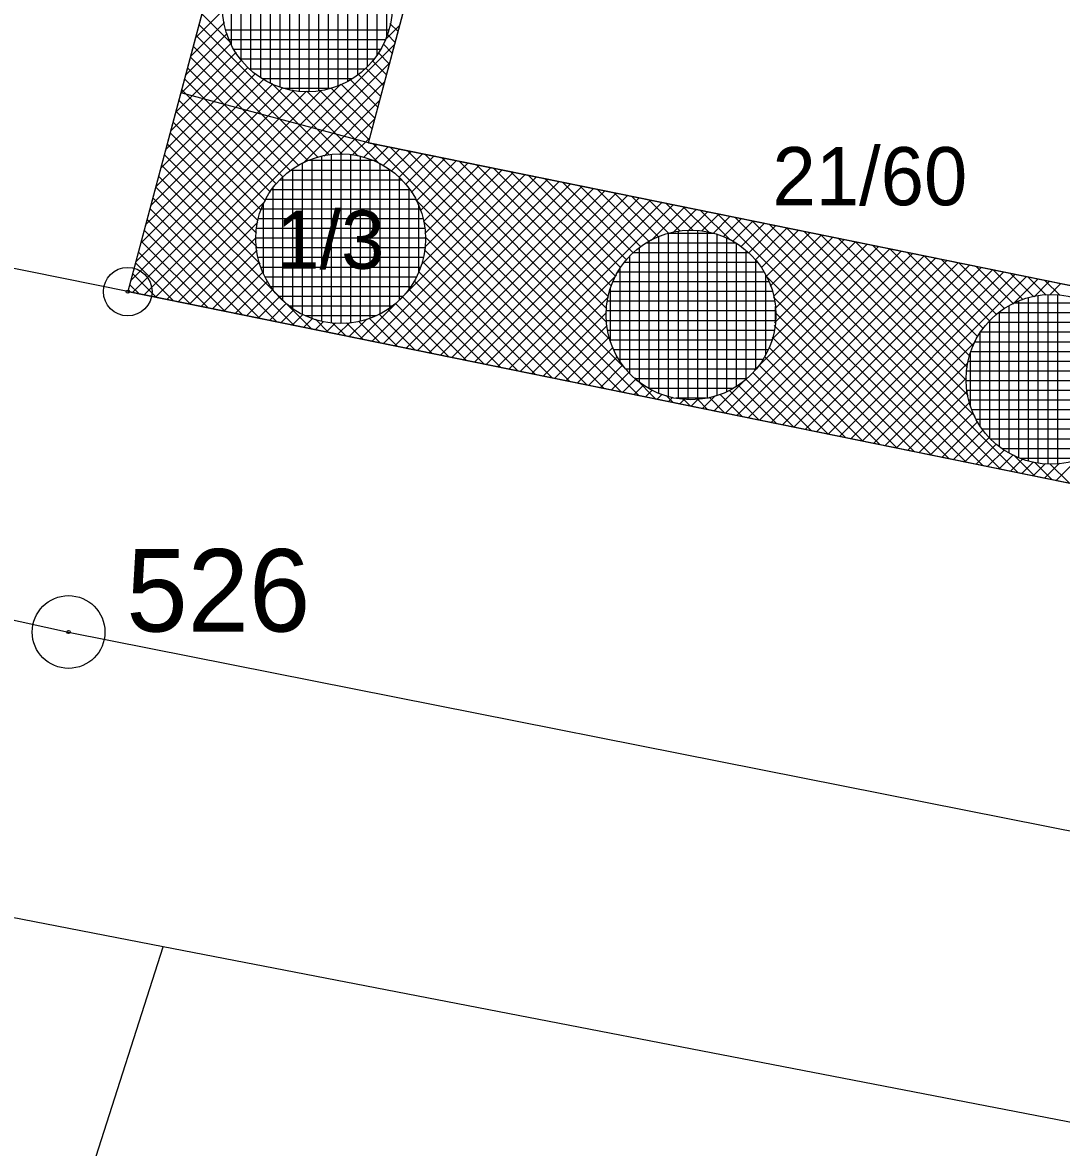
# Model space of a CAD drawing. Extents: x -566461 to -565198, y -1096301 to -1095707.
# Drawn here: x -565856.17 to -565834.75, y -1096125.98 to -1096102.78 of the extents above; entities that cross this region are included whole.
import ezdxf

# ---------------------------------------------------------------- set-up
doc = ezdxf.new("R2010")
doc.units = 0
for name, color, linetype in [('Vrstva 1', 7, 'Continuous'), ('Vrstva 17', 7, 'Continuous'), ('Vrstva 24', 7, 'Continuous'), ('Vrstva 40', 7, 'Continuous'), ('Vrstva 41', 7, 'Continuous'), ('Vrstva 42', 7, 'Continuous'), ('Vrstva 44', 7, 'Continuous')]:
    doc.layers.add(name, color=color, linetype=linetype)

msp = doc.modelspace()

# ---------------------------------------------------------------- linework, layer by layer
at = {"layer": 'Vrstva 1'}
for p, q in [((-565832.07, -1096026.09), (-565854, -1096108.33)), ((-565849.04, -1096105.26), (-565838.03, -1096063.98)), ((-565922.65, -1096100.77), (-565855.22, -1096115.35)), ((-565849.04, -1096105.26), (-565748.22, -1096125.78)), ((-565854, -1096108.33), (-565860.88, -1096106.94)), ((-565697.28, -1096140.23), (-565854, -1096108.33)), ((-565855.22, -1096115.35), (-565699.29, -1096146.31)), ((-565853.27, -1096121.84), (-565856.42, -1096121.23)), ((-565894.7, -1096251.46), (-565853.27, -1096121.84)), ((-565830.85, -1096126.18), (-565853.27, -1096121.84))]:
    msp.add_line(p, q, dxfattribs=at)
at = {"layer": 'Vrstva 24'}
for centre, radius in [((-565854, -1096108.33), 0.5), ((-565854, -1096108.33), 0.0327), ((-565855.22, -1096115.35), 0.75), ((-565855.22, -1096115.35), 0.0327)]:
    msp.add_circle(centre, radius, dxfattribs=at)
at = {"layer": 'Vrstva 41'}
for p, q in [((-565852.604, -1096103.094), (-565852.036, -1096102.526)), ((-565852.472, -1096102.6), (-565851.875, -1096103.197)), ((-565852.707, -1096103.479), (-565852.008, -1096102.781)), ((-565852.532, -1096102.823), (-565849.839, -1096105.516)), ((-565848.705, -1096103.155), (-565848.396, -1096102.846)), ((-565848.596, -1096102.799), (-565848.428, -1096102.967)), ((-565852.809, -1096103.865), (-565851.951, -1096103.007)), ((-565852.591, -1096103.047), (-565850.074, -1096105.564)), ((-565848.655, -1096103.023), (-565848.488, -1096103.19)), ((-565853.665, -1096108.398), (-565848.499, -1096103.232)), ((-565852.912, -1096104.251), (-565851.869, -1096103.208)), ((-565852.651, -1096103.27), (-565850.284, -1096105.636)), ((-565848.738, -1096103.223), (-565848.547, -1096103.413)), ((-565853.118, -1096105.022), (-565851.65, -1096103.554)), ((-565853.015, -1096104.636), (-565851.768, -1096103.39)), ((-565852.71, -1096103.493), (-565850.475, -1096105.729)), ((-565848.84, -1096103.403), (-565848.607, -1096103.637)), ((-565853.43, -1096108.446), (-565848.602, -1096103.617)), ((-565853.221, -1096105.408), (-565851.515, -1096103.702)), ((-565852.77, -1096103.716), (-565850.645, -1096105.841)), ((-565849.096, -1096103.713), (-565848.726, -1096104.083)), ((-565848.96, -1096103.566), (-565848.667, -1096103.86)), ((-565853.426, -1096106.179), (-565851.197, -1096103.95)), ((-565853.324, -1096105.794), (-565851.364, -1096103.834)), ((-565852.829, -1096103.94), (-565850.799, -1096105.97)), ((-565850.385, -1096105.683), (-565848.705, -1096104.003)), ((-565849.417, -1096103.958), (-565848.845, -1096104.53)), ((-565849.248, -1096103.844), (-565848.786, -1096104.306)), ((-565853.941, -1096108.108), (-565850.006, -1096104.173)), ((-565853.9, -1096108.35), (-565849.605, -1096104.055)), ((-565853.838, -1096107.722), (-565850.315, -1096104.199)), ((-565853.735, -1096107.336), (-565850.574, -1096104.176)), ((-565853.632, -1096106.951), (-565850.805, -1096104.124)), ((-565853.529, -1096106.565), (-565851.012, -1096104.048)), ((-565852.889, -1096104.163), (-565850.937, -1096106.115)), ((-565851.037, -1096104.035), (-565849.571, -1096105.501)), ((-565850.621, -1096104.168), (-565849.253, -1096105.536)), ((-565850.307, -1096104.2), (-565848.811, -1096105.695)), ((-565850.045, -1096104.179), (-565849.024, -1096105.2)), ((-565849.812, -1096104.128), (-565848.964, -1096104.976)), ((-565849.603, -1096104.054), (-565848.905, -1096104.753)), ((-565852.948, -1096104.386), (-565851.058, -1096106.277)), ((-565849.953, -1096105.534), (-565848.808, -1096104.389)), ((-565853.008, -1096104.61), (-565851.162, -1096106.456)), ((-565853.067, -1096104.833), (-565851.247, -1096106.653)), ((-565849.636, -1096105.5), (-565848.911, -1096104.775)), ((-565853.127, -1096105.056), (-565851.311, -1096106.872)), ((-565849.371, -1096105.518), (-565849.013, -1096105.16)), ((-565853.187, -1096105.28), (-565851.344, -1096107.122)), ((-565849.137, -1096105.567), (-565848.866, -1096105.295)), ((-565848.944, -1096105.28), (-565843.822, -1096110.402)), ((-565848.927, -1096105.639), (-565848.631, -1096105.343)), ((-565848.738, -1096105.733), (-565848.396, -1096105.391)), ((-565848.589, -1096105.352), (-565843.467, -1096110.474)), ((-565853.246, -1096105.503), (-565851.342, -1096107.407)), ((-565848.568, -1096105.846), (-565848.161, -1096105.439)), ((-565848.415, -1096105.976), (-565847.926, -1096105.487)), ((-565848.278, -1096106.122), (-565847.691, -1096105.535)), ((-565848.234, -1096105.424), (-565843.689, -1096109.969)), ((-565848.157, -1096106.284), (-565847.456, -1096105.582)), ((-565848.054, -1096106.463), (-565847.221, -1096105.63)), ((-565847.879, -1096105.496), (-565844.053, -1096109.322)), ((-565847.523, -1096105.569), (-565844.122, -1096108.97)), ((-565847.168, -1096105.641), (-565844.124, -1096108.685)), ((-565853.306, -1096105.726), (-565851.27, -1096107.761)), ((-565847.969, -1096106.662), (-565846.986, -1096105.678)), ((-565847.954, -1096107.778), (-565846.046, -1096105.869)), ((-565847.906, -1096106.882), (-565846.751, -1096105.726)), ((-565847.889, -1096107.43), (-565846.281, -1096105.822)), ((-565847.875, -1096107.133), (-565846.516, -1096105.774)), ((-565846.813, -1096105.713), (-565844.09, -1096108.437)), ((-565846.458, -1096105.786), (-565844.025, -1096108.218)), ((-565846.103, -1096105.858), (-565843.94, -1096108.021)), ((-565853.365, -1096105.949), (-565850.214, -1096109.101)), ((-565849.2, -1096109.307), (-565845.811, -1096105.917)), ((-565848.965, -1096109.355), (-565845.576, -1096105.965)), ((-565848.73, -1096109.403), (-565845.341, -1096106.013)), ((-565848.495, -1096109.45), (-565845.106, -1096106.061)), ((-565845.748, -1096105.93), (-565843.835, -1096107.843)), ((-565845.393, -1096106.002), (-565843.714, -1096107.682)), ((-565845.038, -1096106.075), (-565843.576, -1096107.537)), ((-565853.425, -1096106.173), (-565850.569, -1096109.028)), ((-565848.26, -1096109.498), (-565844.871, -1096106.109)), ((-565848.025, -1096109.546), (-565844.636, -1096106.156)), ((-565847.79, -1096109.594), (-565844.401, -1096106.204)), ((-565847.555, -1096109.642), (-565844.166, -1096106.252)), ((-565847.32, -1096109.69), (-565843.931, -1096106.3)), ((-565844.682, -1096106.147), (-565843.422, -1096107.408)), ((-565844.327, -1096106.219), (-565843.25, -1096107.296)), ((-565843.972, -1096106.292), (-565843.059, -1096107.204)), ((-565853.484, -1096106.396), (-565850.924, -1096108.956)), ((-565853.195, -1096108.494), (-565851.167, -1096106.465)), ((-565848.065, -1096106.441), (-565844.177, -1096110.329)), ((-565847.085, -1096109.737), (-565843.696, -1096106.348)), ((-565846.85, -1096109.785), (-565843.461, -1096106.396)), ((-565846.615, -1096109.833), (-565843.226, -1096106.443)), ((-565846.38, -1096109.881), (-565842.991, -1096106.491)), ((-565846.145, -1096109.929), (-565842.756, -1096106.539)), ((-565843.617, -1096106.364), (-565842.848, -1096107.133)), ((-565843.262, -1096106.436), (-565842.613, -1096107.085)), ((-565842.907, -1096106.508), (-565842.344, -1096107.072)), ((-565853.544, -1096106.619), (-565851.279, -1096108.884)), ((-565843.209, -1096107.276), (-565842.521, -1096106.587)), ((-565842.76, -1096107.109), (-565842.286, -1096106.635)), ((-565842.552, -1096106.581), (-565842.024, -1096107.108)), ((-565842.44, -1096107.072), (-565842.051, -1096106.683)), ((-565842.197, -1096106.653), (-565841.577, -1096107.272)), ((-565842.17, -1096107.085), (-565841.816, -1096106.73)), ((-565841.934, -1096107.132), (-565841.581, -1096106.778)), ((-565841.841, -1096106.725), (-565836.719, -1096111.847)), ((-565841.486, -1096106.797), (-565836.364, -1096111.92)), ((-565853.603, -1096106.843), (-565851.635, -1096108.811)), ((-565852.96, -1096108.542), (-565851.316, -1096106.897)), ((-565847.906, -1096106.883), (-565844.532, -1096110.257)), ((-565841.723, -1096107.203), (-565841.345, -1096106.826)), ((-565841.532, -1096107.295), (-565841.11, -1096106.874)), ((-565841.36, -1096107.407), (-565840.875, -1096106.922)), ((-565841.206, -1096107.535), (-565840.64, -1096106.97)), ((-565841.131, -1096106.87), (-565836.009, -1096111.992)), ((-565841.068, -1096107.68), (-565840.405, -1096107.017)), ((-565840.776, -1096106.942), (-565835.654, -1096112.064)), ((-565840.421, -1096107.014), (-565836.531, -1096110.904)), ((-565853.663, -1096107.066), (-565851.99, -1096108.739)), ((-565852.725, -1096108.589), (-565851.35, -1096107.214)), ((-565847.871, -1096107.201), (-565844.887, -1096110.185)), ((-565840.946, -1096107.841), (-565840.17, -1096107.065)), ((-565840.841, -1096108.019), (-565839.935, -1096107.113)), ((-565840.755, -1096108.216), (-565839.7, -1096107.161)), ((-565840.691, -1096108.434), (-565839.465, -1096107.209)), ((-565840.656, -1096108.682), (-565839.23, -1096107.257)), ((-565840.066, -1096107.087), (-565836.676, -1096110.476)), ((-565839.711, -1096107.159), (-565836.709, -1096110.161)), ((-565839.356, -1096107.231), (-565836.69, -1096109.896)), ((-565853.722, -1096107.289), (-565852.345, -1096108.667)), ((-565852.49, -1096108.637), (-565851.332, -1096107.479)), ((-565847.892, -1096107.463), (-565845.242, -1096110.113)), ((-565841.68, -1096110.838), (-565838.29, -1096107.448)), ((-565841.445, -1096110.886), (-565838.055, -1096107.496)), ((-565841.078, -1096109.953), (-565838.525, -1096107.4)), ((-565840.726, -1096109.318), (-565838.76, -1096107.352)), ((-565840.666, -1096108.975), (-565838.995, -1096107.305)), ((-565839, -1096107.303), (-565836.641, -1096109.663)), ((-565838.645, -1096107.376), (-565836.568, -1096109.453)), ((-565838.29, -1096107.448), (-565836.474, -1096109.265)), ((-565853.782, -1096107.513), (-565852.7, -1096108.595)), ((-565852.255, -1096108.685), (-565851.283, -1096107.713)), ((-565847.934, -1096107.704), (-565845.597, -1096110.04)), ((-565841.21, -1096110.933), (-565837.82, -1096107.544)), ((-565840.975, -1096110.981), (-565837.585, -1096107.592)), ((-565840.74, -1096111.029), (-565837.35, -1096107.639)), ((-565840.505, -1096111.077), (-565837.115, -1096107.687)), ((-565837.935, -1096107.52), (-565836.36, -1096109.095)), ((-565837.58, -1096107.593), (-565836.23, -1096108.943)), ((-565837.225, -1096107.665), (-565836.084, -1096108.806)), ((-565853.901, -1096107.959), (-565853.41, -1096108.45)), ((-565853.842, -1096107.736), (-565853.055, -1096108.522)), ((-565852.02, -1096108.733), (-565851.211, -1096107.923)), ((-565848.006, -1096107.914), (-565845.953, -1096109.968)), ((-565840.27, -1096111.125), (-565836.88, -1096107.735)), ((-565840.035, -1096111.173), (-565836.645, -1096107.783)), ((-565839.8, -1096111.22), (-565836.41, -1096107.831)), ((-565839.565, -1096111.268), (-565836.175, -1096107.879)), ((-565839.33, -1096111.316), (-565835.94, -1096107.926)), ((-565836.87, -1096107.737), (-565835.921, -1096108.686)), ((-565836.515, -1096107.809), (-565835.741, -1096108.583)), ((-565836.159, -1096107.882), (-565835.543, -1096108.498)), ((-565835.804, -1096107.954), (-565835.322, -1096108.436)), ((-565853.961, -1096108.182), (-565853.765, -1096108.378)), ((-565851.785, -1096108.781), (-565851.117, -1096108.112)), ((-565848.099, -1096108.105), (-565846.308, -1096109.896)), ((-565845.91, -1096109.977), (-565843.924, -1096107.991)), ((-565840.852, -1096107.997), (-565837.074, -1096111.775)), ((-565839.095, -1096111.364), (-565835.705, -1096107.974)), ((-565838.86, -1096111.412), (-565835.47, -1096108.022)), ((-565835.755, -1096108.589), (-565835.235, -1096108.07)), ((-565835.449, -1096108.026), (-565835.07, -1096108.405)), ((-565835.318, -1096108.436), (-565835, -1096108.118)), ((-565835.094, -1096108.099), (-565834.782, -1096108.411)), ((-565835.001, -1096108.402), (-565834.765, -1096108.166)), ((-565851.55, -1096108.829), (-565851.004, -1096108.282)), ((-565848.211, -1096108.275), (-565846.663, -1096109.823)), ((-565851.315, -1096108.876), (-565850.874, -1096108.435)), ((-565851.08, -1096108.924), (-565850.728, -1096108.572)), ((-565848.485, -1096108.567), (-565847.373, -1096109.679)), ((-565848.34, -1096108.429), (-565847.018, -1096109.751)), ((-565845.675, -1096110.024), (-565844.091, -1096108.44)), ((-565840.688, -1096108.444), (-565837.429, -1096111.703)), ((-565850.845, -1096108.972), (-565850.566, -1096108.693)), ((-565850.61, -1096109.02), (-565850.387, -1096108.796)), ((-565850.375, -1096109.068), (-565850.188, -1096108.881)), ((-565849.023, -1096108.877), (-565848.438, -1096109.462)), ((-565848.826, -1096108.792), (-565848.083, -1096109.534)), ((-565848.647, -1096108.688), (-565847.728, -1096109.607)), ((-565845.44, -1096110.072), (-565844.128, -1096108.76)), ((-565840.652, -1096108.764), (-565837.785, -1096111.631)), ((-565850.14, -1096109.116), (-565849.968, -1096108.944)), ((-565850.131, -1096108.9), (-565849.859, -1096109.173)), ((-565849.905, -1096109.163), (-565849.717, -1096108.975)), ((-565849.777, -1096108.972), (-565849.504, -1096109.245)), ((-565849.67, -1096109.211), (-565849.43, -1096108.971)), ((-565849.492, -1096108.974), (-565849.149, -1096109.317)), ((-565849.435, -1096109.259), (-565849.072, -1096108.896)), ((-565849.242, -1096108.941), (-565848.794, -1096109.39)), ((-565845.205, -1096110.12), (-565844.115, -1096109.03)), ((-565840.672, -1096109.026), (-565838.14, -1096111.558)), ((-565844.97, -1096110.168), (-565844.068, -1096109.266)), ((-565840.713, -1096109.268), (-565838.495, -1096111.486)), ((-565838.625, -1096111.46), (-565836.521, -1096109.355)), ((-565844.735, -1096110.216), (-565843.997, -1096109.477)), ((-565840.784, -1096109.479), (-565838.85, -1096111.414)), ((-565844.5, -1096110.264), (-565843.905, -1096109.668)), ((-565840.876, -1096109.67), (-565839.205, -1096111.341)), ((-565838.39, -1096111.507), (-565836.674, -1096109.792)), ((-565844.265, -1096110.312), (-565843.793, -1096109.84)), ((-565844.03, -1096110.359), (-565843.665, -1096109.994)), ((-565841.117, -1096109.996), (-565839.915, -1096111.197)), ((-565840.988, -1096109.842), (-565839.56, -1096111.269)), ((-565843.795, -1096110.407), (-565843.52, -1096110.132)), ((-565843.56, -1096110.455), (-565843.359, -1096110.254)), ((-565843.549, -1096110.109), (-565843.111, -1096110.546)), ((-565841.915, -1096110.79), (-565841.247, -1096110.122)), ((-565841.423, -1096110.255), (-565840.626, -1096111.052)), ((-565841.262, -1096110.134), (-565840.27, -1096111.125)), ((-565838.155, -1096111.555), (-565836.708, -1096110.109)), ((-565843.325, -1096110.503), (-565843.181, -1096110.359)), ((-565843.09, -1096110.551), (-565842.984, -1096110.445)), ((-565842.902, -1096110.473), (-565842.756, -1096110.619)), ((-565842.855, -1096110.599), (-565842.766, -1096110.509)), ((-565842.15, -1096110.742), (-565841.882, -1096110.474)), ((-565842.017, -1096110.51), (-565841.691, -1096110.835)), ((-565841.798, -1096110.445), (-565841.336, -1096110.908)), ((-565841.601, -1096110.36), (-565840.981, -1096110.98)), ((-565837.92, -1096111.603), (-565836.692, -1096110.375)), ((-565842.62, -1096110.646), (-565842.518, -1096110.544)), ((-565842.55, -1096110.542), (-565842.401, -1096110.691)), ((-565842.385, -1096110.694), (-565842.233, -1096110.542)), ((-565842.265, -1096110.544), (-565842.046, -1096110.763)), ((-565837.685, -1096111.651), (-565836.643, -1096110.609)), ((-565837.45, -1096111.699), (-565836.571, -1096110.82)), ((-565837.215, -1096111.747), (-565836.477, -1096111.009)), ((-565836.98, -1096111.794), (-565836.365, -1096111.179)), ((-565836.745, -1096111.842), (-565836.235, -1096111.332)), ((-565836.51, -1096111.89), (-565836.089, -1096111.469)), ((-565836.275, -1096111.938), (-565835.927, -1096111.59)), ((-565836.04, -1096111.986), (-565835.748, -1096111.694)), ((-565835.805, -1096112.034), (-565835.55, -1096111.779)), ((-565835.734, -1096111.701), (-565835.299, -1096112.137)), ((-565835.57, -1096112.081), (-565835.331, -1096111.842)), ((-565835.335, -1096112.129), (-565835.08, -1096111.874)), ((-565835.306, -1096111.846), (-565834.944, -1096112.209)), ((-565835.1, -1096112.177), (-565834.793, -1096111.87)), ((-565834.991, -1096111.879), (-565834.588, -1096112.281)), ((-565834.865, -1096112.225), (-565834.436, -1096111.796))]:
    msp.add_line(p, q, dxfattribs=at)
at = {"layer": 'Vrstva 42'}
msp.add_line((-565849.04, -1096105.26), (-565852.906, -1096104.229), dxfattribs=at)
msp.add_lwpolyline([(-565828.2, -1096027.12), (-565826.72, -1096023.51), (-565829.55, -1096025.32), (-565832.07, -1096026.09), (-565854, -1096108.33), (-565697.28, -1096140.23), (-565696.05, -1096136.4), (-565849.04, -1096105.26)], close=True, dxfattribs=at)
at = {"layer": 'Vrstva 44'}
for p, q in [((-565850.66, -1096104.172), (-565850.66, -1096100.749)), ((-565850.46, -1096104.201), (-565850.46, -1096100.718)), ((-565850.26, -1096104.208), (-565850.26, -1096100.711)), ((-565850.06, -1096104.192), (-565850.06, -1096100.728)), ((-565849.86, -1096104.153), (-565849.86, -1096100.768)), ((-565851.26, -1096103.923), (-565851.26, -1096100.998)), ((-565851.06, -1096104.035), (-565851.06, -1096100.885)), ((-565850.86, -1096104.116), (-565850.86, -1096100.804)), ((-565849.66, -1096104.087), (-565849.66, -1096100.833)), ((-565849.46, -1096103.993), (-565849.46, -1096100.926)), ((-565851.46, -1096103.768), (-565851.46, -1096101.152)), ((-565849.26, -1096103.867), (-565849.26, -1096101.055)), ((-565849.06, -1096103.692), (-565849.06, -1096101.226)), ((-565851.66, -1096103.559), (-565851.66, -1096101.362)), ((-565848.86, -1096103.451), (-565848.86, -1096101.466)), ((-565851.86, -1096103.249), (-565851.86, -1096101.671)), ((-565848.66, -1096103.071), (-565848.66, -1096101.855)), ((-565848.618, -1096102.94), (-565851.981, -1096102.94)), ((-565848.69, -1096103.14), (-565851.911, -1096103.14)), ((-565848.789, -1096103.34), (-565851.812, -1096103.34)), ((-565848.925, -1096103.54), (-565851.674, -1096103.54)), ((-565849.108, -1096103.74), (-565851.492, -1096103.74)), ((-565849.368, -1096103.94), (-565851.232, -1096103.94)), ((-565849.815, -1096104.14), (-565850.789, -1096104.14)), ((-565848.925, -1096105.63), (-565850.291, -1096105.63)), ((-565850.2, -1096108.886), (-565850.2, -1096105.594)), ((-565850, -1096108.946), (-565850, -1096105.536)), ((-565849.8, -1096108.979), (-565849.8, -1096105.502)), ((-565849.6, -1096108.988), (-565849.6, -1096105.491)), ((-565849.4, -1096108.975), (-565849.4, -1096105.503)), ((-565849.2, -1096108.94), (-565849.2, -1096105.541)), ((-565849, -1096108.88), (-565849, -1096105.602)), ((-565848.577, -1096105.83), (-565850.644, -1096105.83)), ((-565850.6, -1096108.681), (-565850.6, -1096105.799)), ((-565850.4, -1096108.801), (-565850.4, -1096105.679)), ((-565848.8, -1096108.789), (-565848.8, -1096105.69)), ((-565848.6, -1096108.667), (-565848.6, -1096105.813)), ((-565848.348, -1096106.03), (-565850.872, -1096106.03)), ((-565850.8, -1096108.522), (-565850.8, -1096105.957)), ((-565848.4, -1096108.502), (-565848.4, -1096105.977)), ((-565848.182, -1096106.23), (-565851.038, -1096106.23)), ((-565851, -1096108.3), (-565851, -1096106.179)), ((-565848.2, -1096108.275), (-565848.2, -1096106.206)), ((-565851.2, -1096107.97), (-565851.2, -1096106.51)), ((-565848.06, -1096106.43), (-565851.159, -1096106.43)), ((-565848, -1096107.921), (-565848, -1096106.556)), ((-565847.972, -1096106.63), (-565851.249, -1096106.63)), ((-565847.873, -1096107.03), (-565851.346, -1096107.03)), ((-565847.91, -1096106.83), (-565851.311, -1096106.83)), ((-565847.861, -1096107.23), (-565851.358, -1096107.23)), ((-565843.05, -1096110.43), (-565843.05, -1096107.191)), ((-565841.905, -1096107.13), (-565842.877, -1096107.13)), ((-565842.85, -1096110.498), (-565842.85, -1096107.122)), ((-565842.65, -1096110.539), (-565842.65, -1096107.081)), ((-565842.45, -1096110.558), (-565842.45, -1096107.063)), ((-565842.25, -1096110.553), (-565842.25, -1096107.067)), ((-565842.05, -1096110.525), (-565842.05, -1096107.094)), ((-565841.85, -1096110.473), (-565841.85, -1096107.146)), ((-565841.65, -1096110.395), (-565841.65, -1096107.226)), ((-565847.872, -1096107.43), (-565851.348, -1096107.43)), ((-565843.45, -1096110.201), (-565843.45, -1096107.418)), ((-565841.459, -1096107.33), (-565843.323, -1096107.33)), ((-565843.25, -1096110.332), (-565843.25, -1096107.288)), ((-565841.45, -1096110.284), (-565841.45, -1096107.335)), ((-565841.25, -1096110.136), (-565841.25, -1096107.484)), ((-565847.906, -1096107.63), (-565851.315, -1096107.63)), ((-565841.015, -1096107.73), (-565843.765, -1096107.73)), ((-565843.65, -1096110.022), (-565843.65, -1096107.598)), ((-565841.199, -1096107.53), (-565843.583, -1096107.53)), ((-565841.05, -1096109.933), (-565841.05, -1096107.685)), ((-565847.963, -1096107.83), (-565851.256, -1096107.83)), ((-565840.879, -1096107.93), (-565843.902, -1096107.93)), ((-565843.85, -1096109.772), (-565843.85, -1096107.849)), ((-565848.05, -1096108.03), (-565851.169, -1096108.03)), ((-565840.778, -1096108.13), (-565844, -1096108.13)), ((-565840.85, -1096109.637), (-565840.85, -1096107.98)), ((-565848.169, -1096108.23), (-565851.052, -1096108.23)), ((-565840.709, -1096108.33), (-565844.071, -1096108.33)), ((-565844.05, -1096109.362), (-565844.05, -1096108.261)), ((-565835.23, -1096111.869), (-565835.23, -1096108.411)), ((-565835.03, -1096111.888), (-565835.03, -1096108.393)), ((-565834.83, -1096111.883), (-565834.83, -1096108.397)), ((-565848.328, -1096108.43), (-565850.89, -1096108.43)), ((-565848.548, -1096108.63), (-565850.671, -1096108.63)), ((-565840.664, -1096108.53), (-565844.117, -1096108.53)), ((-565840.65, -1096108.98), (-565840.65, -1096108.638)), ((-565835.83, -1096111.662), (-565835.83, -1096108.618)), ((-565834.201, -1096108.57), (-565835.742, -1096108.57)), ((-565835.63, -1096111.76), (-565835.63, -1096108.521)), ((-565835.43, -1096111.828), (-565835.43, -1096108.452)), ((-565848.882, -1096108.83), (-565850.336, -1096108.83)), ((-565840.643, -1096108.73), (-565844.137, -1096108.73)), ((-565833.883, -1096108.77), (-565836.057, -1096108.77)), ((-565836.03, -1096111.531), (-565836.03, -1096108.748)), ((-565840.644, -1096108.93), (-565844.134, -1096108.93)), ((-565833.671, -1096108.97), (-565836.271, -1096108.97)), ((-565836.23, -1096111.352), (-565836.23, -1096108.928)), ((-565840.671, -1096109.13), (-565844.108, -1096109.13)), ((-565840.721, -1096109.33), (-565844.059, -1096109.33)), ((-565836.43, -1096111.102), (-565836.43, -1096109.179)), ((-565833.515, -1096109.17), (-565836.424, -1096109.17)), ((-565840.797, -1096109.53), (-565843.985, -1096109.53)), ((-565833.317, -1096109.57), (-565836.624, -1096109.57)), ((-565833.401, -1096109.37), (-565836.54, -1096109.37)), ((-565840.902, -1096109.73), (-565843.876, -1096109.73)), ((-565833.26, -1096109.77), (-565836.679, -1096109.77)), ((-565836.63, -1096110.692), (-565836.63, -1096109.591)), ((-565841.048, -1096109.93), (-565843.733, -1096109.93)), ((-565833.23, -1096109.97), (-565836.71, -1096109.97)), ((-565841.243, -1096110.13), (-565843.536, -1096110.13)), ((-565833.222, -1096110.17), (-565836.718, -1096110.17)), ((-565841.526, -1096110.33), (-565843.253, -1096110.33)), ((-565833.237, -1096110.37), (-565836.704, -1096110.37)), ((-565842.074, -1096110.53), (-565842.702, -1096110.53)), ((-565833.275, -1096110.57), (-565836.665, -1096110.57)), ((-565833.338, -1096110.77), (-565836.601, -1096110.77)), ((-565833.432, -1096110.97), (-565836.509, -1096110.97)), ((-565833.556, -1096111.17), (-565836.383, -1096111.17)), ((-565833.728, -1096111.37), (-565836.213, -1096111.37)), ((-565833.964, -1096111.57), (-565835.975, -1096111.57)), ((-565834.336, -1096111.77), (-565835.605, -1096111.77))]:
    msp.add_line(p, q, dxfattribs=at)
for centre in [(-565850.3, -1096102.46), (-565849.61, -1096107.24), (-565842.39, -1096108.81), (-565834.97, -1096110.14)]:
    msp.add_circle(centre, 1.75, dxfattribs=at)

# ---------------------------------------------------------------- texts
at = {"layer": 'Vrstva 17'}
msp.add_text('526', height=1.7, dxfattribs=at).set_placement((-565854.03, -1096115.34))
at = {"layer": 'Vrstva 40'}
for s, p in [('21/60', (-565840.71, -1096106.55)), ('1/3', (-565850.94, -1096107.86))]:
    msp.add_text(s, height=1.2, dxfattribs=at).set_placement(p)

doc.saveas('drawing.dxf')
